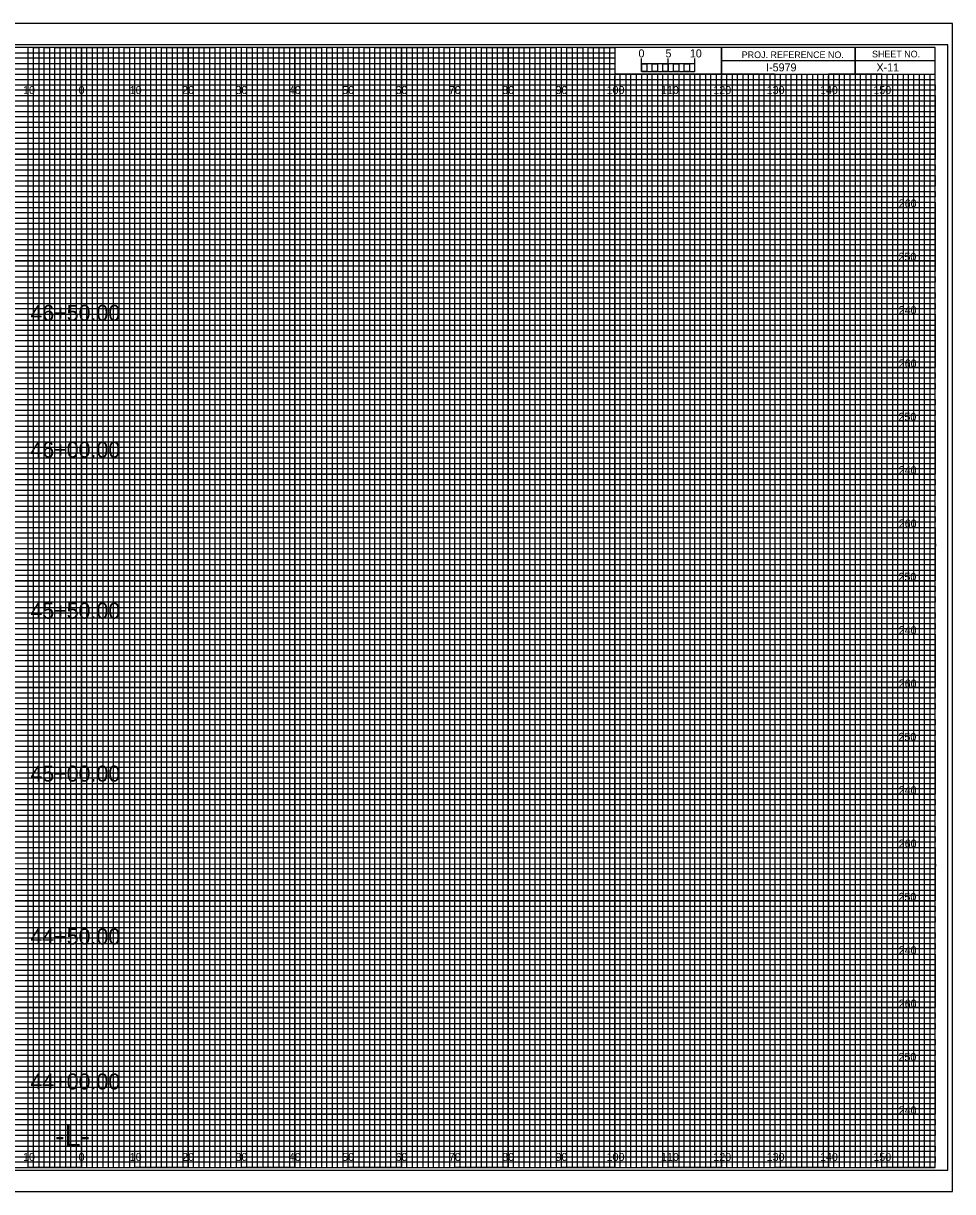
# Model space of a CAD drawing. Extents: x -13 to 359, y -5 to 2854.
# Drawn here: x 149.1 to 323.3, y 2195.5 to 2414.5 of the extents above; entities that cross this region are included whole.
import ezdxf

# ---------------------------------------------------------------- set-up
doc = ezdxf.new("R2010")
doc.units = 0
for name, color, linetype in [('Exist CMT Pavement', 7, 'Continuous'), ('Exist Cross Section Cell', 7, 'Continuous'), ('Exist XS Ground Line', 7, 'Continuous'), ('Prop CMT Conc Surface', 7, 'Continuous'), ('Prop CMT Concrete Structures', 7, 'Continuous'), ('Prop CMT DNC', 7, 'Continuous'), ('Prop CMT Pvmt Course 1', 7, 'Continuous'), ('Prop CMT Pvmt Course 1 CG', 7, 'Continuous'), ('Prop CMT Pvmt Course 1 Wedge', 7, 'Continuous'), ('Prop CMT Pvmt Course 2', 7, 'Continuous'), ('Prop CMT Pvmt Course 2 Wedge', 7, 'Continuous'), ('Prop CMT Pvmt Course 3', 7, 'Continuous'), ('Prop CMT Pvmt Course 3 Wedge', 7, 'Continuous'), ('Prop CMT Shear Line', 7, 'Continuous'), ('Prop CMT Slope Grass', 7, 'Continuous'), ('Prop CMT Subgrade Earthwork', 7, 'Continuous'), ('Scratch_Level_0', 7, 'Continuous')]:
    doc.layers.add(name, color=color, linetype=linetype)

msp = doc.modelspace()

# ---------------------------------------------------------------- linework, layer by layer
at = {"layer": 'Exist XS Ground Line'}
for p, q in [((150, 2410), (140, 2410)), ((150, 2200), (150, 2410)), ((170, 2410), (160, 2410)), ((160, 2410), (160, 2200)), ((170, 2200), (170, 2410)), ((190, 2410), (180, 2410)), ((180, 2410), (180, 2200)), ((190, 2200), (190, 2410)), ((210, 2410), (200, 2410)), ((200, 2410), (200, 2200)), ((210, 2200), (210, 2410)), ((230, 2410), (220, 2410)), ((220, 2410), (220, 2200)), ((230, 2200), (230, 2410)), ((250, 2410), (240, 2410)), ((240, 2410), (240, 2200)), ((250, 2200), (250, 2410)), ((260, 2410), (260, 2200)), ((270, 2200), (270, 2405)), ((290, 2405), (280, 2405)), ((280, 2405), (280, 2200)), ((290, 2200), (290, 2405)), ((310, 2405), (300, 2405)), ((300, 2405), (300, 2200)), ((310, 2200), (310, 2405)), ((160, 2200), (150, 2200)), ((180, 2200), (170, 2200)), ((200, 2200), (190, 2200)), ((220, 2200), (210, 2200)), ((240, 2200), (230, 2200)), ((260, 2200), (250, 2200)), ((280, 2200), (270, 2200)), ((300, 2200), (290, 2200)), ((320, 2200), (310, 2200)), ((320, 2200), (320, 2200))]:
    msp.add_line(p, q, dxfattribs=at)
for points in [[(0, 2400), (320, 2400), (320, 2390), (0, 2390)], [(0, 2380), (320, 2380), (320, 2370), (0, 2370)], [(0, 2360), (320, 2360), (320, 2350), (0, 2350)], [(0, 2340), (320, 2340), (320, 2330), (0, 2330)], [(0, 2320), (320, 2320), (320, 2310), (0, 2310)], [(0, 2300), (320, 2300), (320, 2290), (0, 2290)], [(0, 2280), (320, 2280), (320, 2270), (0, 2270)], [(0, 2260), (320, 2260), (320, 2250), (0, 2250)], [(0, 2240), (320, 2240), (320, 2230), (0, 2230)], [(0, 2220), (320, 2220), (320, 2210), (0, 2210)]]:
    msp.add_lwpolyline(points, dxfattribs=at)
at = {"layer": 'Prop CMT Conc Surface'}
for p, q in [((265, 2405.49), (265, 2407.9)), ((265, 2406.9), (265, 2407.9)), ((270, 2405.49), (270, 2407.9)), ((275, 2405.49), (275, 2407.9)), ((275, 2406.9), (275, 2407.9))]:
    msp.add_line(p, q, dxfattribs=at)
for points in [[(275, 2406.9), (265, 2406.9), (265, 2405.49), (275, 2405.49)], [(265, 2406.9), (266, 2406.9), (266, 2405.49), (265, 2405.49)], [(267, 2406.9), (268, 2406.9), (268, 2405.49), (267, 2405.49)], [(269, 2406.9), (270, 2406.9), (270, 2405.49), (269, 2405.49)], [(271, 2406.9), (272, 2406.9), (272, 2405.49), (271, 2405.49)], [(273, 2406.9), (274, 2406.9), (274, 2405.49), (273, 2405.49)]]:
    msp.add_lwpolyline(points, close=True, dxfattribs=at)
at = {"layer": 'Prop CMT Concrete Structures'}
for p, q in [((305, 2410), (305, 2405)), ((305, 2405), (305, 2410)), ((280, 2407.5), (280, 2405)), ((320, 2407.49), (280, 2407.49)), ((280, 2405), (320, 2405))]:
    msp.add_line(p, q, dxfattribs=at)
for points in [[(320, 2410), (0, 2410), (0, 2200), (320, 2200)], [(280, 2410), (260, 2410), (260, 2405.03), (280, 2405.03)], [(320, 2410), (280, 2410), (280, 2405), (320, 2405)]]:
    msp.add_lwpolyline(points, close=True, dxfattribs=at)
at = {"layer": 'Prop CMT DNC'}
for p, q in [((323.3, 2414.5), (-13.4, 2414.5)), ((-13.4, 2195.5), (323.3, 2195.5))]:
    msp.add_line(p, q, dxfattribs=at)
at = {"layer": 'Prop CMT Pvmt Course 1'}
for p, q in [((0, 2409), (260, 2409)), ((260, 2409), (260, 2407.98)), ((260, 2407.98), (0, 2407.98)), ((0, 2407), (260, 2407)), ((260, 2407), (260, 2405.89)), ((260, 2405.89), (0, 2405.89)), ((0, 2404), (320, 2404))]:
    msp.add_line(p, q, dxfattribs=at)
for points in [[(0, 2403), (270, 2403), (320, 2403), (320, 2402), (0, 2402)], [(0, 2401), (320, 2401), (320, 2399), (0, 2399)], [(0, 2398), (320, 2398), (320, 2397), (0, 2396.98)], [(0, 2396), (320, 2396), (320, 2394), (0, 2394)], [(0, 2393), (320, 2393), (320, 2392), (0, 2392)], [(0, 2391), (320, 2391), (320, 2389), (0, 2389)], [(0, 2388), (320, 2388), (320, 2387), (0, 2387)], [(0, 2386), (320, 2386), (320, 2384), (0, 2384)], [(0, 2383), (320, 2383), (320, 2382), (0, 2382)], [(0, 2381), (320, 2381), (320, 2379), (0, 2379)], [(0, 2378), (320, 2378), (320, 2377), (0, 2377)], [(0, 2376), (320, 2376), (320, 2373.95), (320, 2373), (320, 2372), (0, 2372)], [(0, 2374), (320, 2374), (320, 2373), (0, 2373)], [(0, 2371), (320, 2371), (320, 2369), (0, 2369.03)], [(0, 2369.03), (320, 2369), (320, 2368), (0, 2368)], [(0, 2367), (320, 2367), (320, 2366), (0, 2366)], [(0, 2364), (320, 2364), (320, 2363), (0, 2363)], [(0, 2362), (320, 2362), (320, 2361), (0, 2361)], [(-0.07, 2358.89), (320, 2358.89), (320, 2357.88), (-0.07, 2357.88)], [(0, 2357), (320, 2357), (320, 2356), (0, 2356)], [(0, 2354), (320, 2354), (320, 2353), (0, 2353)], [(0, 2352), (320, 2352), (320, 2351), (0, 2351)], [(0, 2349), (320, 2349), (320, 2348), (0, 2348)], [(0, 2347), (320, 2347), (320, 2346), (0, 2346)], [(0, 2344), (320, 2344), (320, 2343), (0, 2343)], [(0, 2342), (320, 2342), (320, 2341), (0, 2341)], [(0, 2339), (320, 2339), (319.99, 2337.98), (0, 2338)], [(0, 2337), (320, 2337), (320, 2336), (0, 2336)], [(0, 2334), (320, 2334), (320, 2333), (0, 2333)], [(0, 2332), (320, 2332), (320, 2331), (0, 2331)], [(0, 2329), (320, 2329), (320, 2328), (0, 2328)], [(0, 2327), (320, 2327), (320, 2326), (0, 2326)], [(0, 2324), (320, 2324), (320, 2323), (0, 2323)], [(0, 2322), (320, 2322), (320, 2321), (0, 2321)], [(0, 2319), (320, 2319), (320, 2318), (0, 2318)], [(0, 2316.99), (320.07, 2316.91), (320, 2316), (0, 2316)], [(0, 2314), (320, 2314), (320, 2313), (0, 2313)], [(0, 2312), (320, 2312), (320, 2311), (0, 2311)], [(0, 2309), (320, 2309), (320, 2308), (0, 2308)], [(0, 2307), (320, 2307), (320, 2306), (0, 2306)], [(0, 2304), (320, 2304), (320, 2303), (0, 2303)], [(0, 2302), (320, 2302), (320, 2301), (0, 2301)], [(0, 2299), (320, 2299), (320, 2298), (0, 2298)], [(0, 2297), (320, 2297), (320, 2296), (0, 2296)], [(0, 2294), (320, 2294), (320, 2293), (0, 2293)], [(0, 2292), (320, 2292), (320, 2291), (0, 2291)], [(0, 2289), (320, 2289), (320, 2288), (0, 2288)], [(0, 2287), (320, 2287), (320, 2286), (0, 2286)], [(0, 2284), (320, 2284), (320, 2283), (0, 2283)], [(0, 2282), (320, 2282), (320, 2281), (0, 2281)], [(0, 2279), (320, 2279), (319.99, 2277.98), (0, 2278)], [(0, 2277), (320, 2277), (320, 2276), (0, 2276)], [(0, 2274), (320, 2274), (320, 2273), (0, 2273)], [(0, 2272), (320, 2272), (320, 2271), (0, 2271)], [(0, 2269), (320, 2269), (320, 2268), (0, 2268)], [(0, 2267), (320, 2267), (320, 2266), (0, 2266)], [(0, 2264), (320, 2264), (320, 2263), (0, 2263)], [(0, 2262), (320, 2262), (320, 2261), (0, 2261)], [(0, 2259), (320, 2259), (320, 2258), (0, 2258)], [(0, 2256.99), (320.07, 2256.91), (320, 2256), (0, 2256)], [(0, 2254), (320, 2254), (320, 2253), (0, 2253)], [(0, 2252), (320, 2252), (320, 2251), (0, 2251)], [(0, 2249), (320, 2249), (320, 2248), (0, 2248)], [(0, 2247), (320, 2247), (320, 2246), (0, 2246)], [(0, 2244), (320, 2244), (320, 2243), (0, 2243)], [(0, 2242), (320, 2242), (320, 2241), (0, 2241)], [(0, 2239), (320, 2239), (320, 2238), (0, 2238)], [(0, 2237), (320, 2237), (320, 2236), (0, 2236)], [(0, 2234), (320, 2234), (320, 2233), (0, 2233)], [(0, 2232), (320, 2232), (320, 2231), (0, 2231)], [(0, 2229), (320, 2229), (320, 2228), (0, 2228)], [(0, 2227), (320, 2227), (320, 2226), (0, 2226)], [(0, 2224), (320, 2224), (320, 2223), (0, 2223)], [(0, 2222), (320, 2222), (320, 2221), (0, 2221)], [(0, 2219), (320, 2219), (320, 2218), (0, 2218)], [(0, 2217), (320, 2217), (320, 2216), (0, 2216)], [(0, 2214), (320, 2214), (320, 2213), (0, 2213)], [(0, 2212), (320, 2212), (320, 2211), (0, 2211)], [(0, 2209), (320, 2209), (320, 2208), (0, 2208)], [(0, 2207), (320, 2207), (320, 2206), (0, 2206)], [(0, 2204), (320, 2204), (320, 2203), (0, 2203)], [(0, 2202), (320, 2202), (320, 2201), (0, 2201)]]:
    msp.add_lwpolyline(points, dxfattribs=at)
at = {"layer": 'Prop CMT Pvmt Course 1 CG'}
for p, q in [((267, 2405), (266.01, 2405)), ((266.01, 2405), (266.01, 2200)), ((267, 2200), (267, 2405)), ((269, 2405), (268, 2405)), ((268, 2405), (268, 2200)), ((269, 2200), (269, 2405)), ((266.01, 2200), (265, 2200)), ((268, 2200), (267, 2200))]:
    msp.add_line(p, q, dxfattribs=at)
for points in [[(150, 2200), (151, 2200), (151, 2410), (152, 2410), (152, 2200)], [(152, 2200), (153, 2200), (153, 2410), (154, 2410), (154, 2200)], [(155, 2200), (156, 2200), (156, 2410), (157, 2410), (157, 2200)], [(157, 2200), (158, 2200), (158, 2410), (159, 2410), (159, 2200)], [(160, 2200), (161, 2200), (161, 2410), (162, 2410), (162, 2200)], [(162, 2200), (163, 2200), (163, 2410), (164, 2410), (164, 2200)], [(165, 2200), (166, 2200), (166, 2410), (167, 2410), (167, 2200)], [(167, 2200), (168, 2200), (168, 2410), (169, 2410), (169, 2200)], [(170, 2200), (171, 2200), (171, 2410), (172, 2410), (172, 2200)], [(172, 2200), (173, 2200), (173, 2410), (174, 2410), (174, 2200)], [(175, 2200), (176, 2200), (176, 2410), (177, 2410), (177, 2200)], [(177, 2200), (178, 2200), (178, 2410), (179, 2410), (179, 2200)], [(180, 2200), (181, 2200), (181, 2410), (182, 2410), (182, 2200)], [(182, 2200), (183, 2200), (183, 2410), (184, 2410), (184, 2200)], [(185, 2200), (186, 2200), (186, 2410), (187, 2410), (187, 2200)], [(187, 2200), (188, 2200), (188, 2410), (189, 2410), (189, 2200)], [(190, 2200), (191, 2200), (191, 2410), (192, 2410), (192, 2200)], [(192, 2200), (193, 2200), (193, 2410), (194, 2410), (194, 2200)], [(195, 2200), (196, 2200), (196, 2410), (197, 2410), (197, 2200)], [(197, 2200), (198, 2200), (198, 2410), (199, 2410), (199, 2200)], [(200, 2200), (201, 2200), (201, 2410), (202, 2410), (202, 2200)], [(202, 2200), (203, 2200), (203, 2410), (204, 2410), (204, 2200)], [(205, 2200), (206, 2200), (206, 2410), (207, 2410), (207, 2200)], [(207, 2200), (208, 2200), (208, 2410), (209, 2410), (209, 2200)], [(210, 2200), (211, 2200), (211, 2410), (212, 2410), (212, 2200)], [(212, 2200), (213, 2200), (213, 2410), (214, 2410), (214, 2200)], [(215, 2200), (216, 2200), (216, 2410), (217, 2410), (217, 2200)], [(217, 2200), (218, 2200), (218, 2410), (219, 2410), (219, 2200)], [(220, 2200), (221, 2200), (221, 2410), (222, 2410), (222, 2200)], [(222, 2200), (223, 2200), (223, 2410), (224, 2410), (224, 2200)], [(225, 2200), (226, 2200), (226, 2410), (227, 2410), (227, 2200)], [(227, 2200), (228, 2200), (228, 2410), (229, 2410), (229, 2200)], [(230, 2200), (231, 2200), (231, 2410), (232, 2410), (232, 2200)], [(232, 2200), (233, 2200), (233, 2410), (234, 2410), (234, 2200)], [(235, 2200), (236, 2200), (236, 2410), (237, 2410), (237, 2200)], [(237, 2200), (238, 2200), (238, 2410), (239, 2410), (239, 2200)], [(240, 2200), (241, 2200), (241, 2410), (242, 2410), (242, 2200)], [(242, 2200), (243, 2200), (243, 2410), (244, 2410), (244, 2200)], [(245, 2200), (246, 2200), (246, 2410), (247, 2410), (247, 2200)], [(247, 2200), (248, 2200), (248, 2410), (249, 2410), (249, 2200)], [(250, 2200), (251, 2200), (251, 2410), (252, 2410), (252, 2200)], [(252, 2200), (253, 2200), (253, 2410), (254, 2410), (254, 2200)], [(255, 2200), (256, 2200), (256, 2410), (257, 2410), (257, 2200)], [(257, 2200), (258, 2200), (258, 2410), (259, 2410), (259, 2200)], [(260, 2200), (261, 2200), (261, 2405), (262.02, 2405), (262.02, 2200)], [(262, 2200), (263, 2200), (263, 2405), (263.99, 2405), (263.99, 2200)], [(270, 2200), (270.98, 2200), (270.98, 2405), (272, 2405), (272, 2200)], [(272, 2200), (273, 2200), (273, 2405), (274.05, 2405), (274.05, 2200)], [(275, 2200), (276, 2200), (276, 2405), (277, 2405), (277, 2200)], [(277, 2200), (278, 2200), (278, 2405), (279, 2405), (279, 2200)], [(280, 2200), (281, 2200), (281, 2405), (282, 2405), (282, 2200)], [(282, 2200), (283, 2200), (283, 2405), (284, 2405), (284, 2200)], [(285, 2200), (286, 2200), (286, 2405), (287, 2405), (287, 2200)], [(287, 2200), (288, 2200), (288, 2405), (289, 2405), (289, 2200)], [(290, 2200), (291, 2200), (291, 2405), (292, 2405), (292, 2200)], [(292, 2200), (293, 2200), (293, 2405), (294, 2405), (294, 2200)], [(295, 2200), (296, 2200), (296, 2405), (297, 2405), (297, 2200)], [(297, 2200), (298, 2200), (298, 2405), (299, 2405), (299, 2200)], [(300, 2200), (301, 2200), (301, 2405), (302, 2405), (302, 2200)], [(302, 2200), (303, 2200), (303, 2405), (304, 2405), (304, 2200)], [(305, 2200), (306, 2200), (306, 2405), (307, 2405), (307, 2200)], [(307, 2200), (308, 2200), (308, 2405), (309, 2405), (309, 2200)], [(310, 2200), (311, 2200), (311, 2405), (312, 2405), (312, 2200)], [(312, 2200), (313, 2200), (313, 2405), (314, 2405), (314, 2200)], [(315, 2200), (316, 2200), (316, 2405), (317, 2405), (317, 2200)], [(317, 2200), (318, 2200), (318, 2405), (319, 2405), (319, 2200)]]:
    msp.add_lwpolyline(points, dxfattribs=at)
at = {"layer": 'Prop CMT Shear Line'}
for p, q in [((150, 2200), (150, 2410)), ((160, 2200), (160, 2410)), ((170, 2200), (170, 2410)), ((180, 2200), (180, 2410)), ((190, 2200), (190, 2410)), ((200, 2200), (200, 2410)), ((210, 2200), (210, 2410)), ((220, 2200), (220, 2410)), ((230, 2200), (230, 2410)), ((240, 2200), (240, 2410)), ((250, 2200), (250, 2410)), ((260, 2200), (260, 2404.69)), ((270, 2200), (270, 2404.69)), ((280, 2200), (280, 2404.69)), ((290, 2200), (290, 2404.69)), ((300, 2200), (300, 2404.69)), ((310, 2200), (310, 2404.69)), ((0, 2400), (320, 2400)), ((0, 2390), (320, 2390)), ((0, 2380), (320, 2380)), ((0, 2370), (320, 2370)), ((0, 2360), (320, 2360)), ((0, 2350), (320, 2350)), ((0, 2340), (320, 2340)), ((0, 2330), (320, 2330)), ((0, 2320), (320, 2320)), ((0, 2310), (320, 2310)), ((0, 2300), (320, 2300)), ((0, 2290), (320, 2290)), ((0, 2280), (320, 2280)), ((0, 2270), (320, 2270)), ((0, 2260), (320, 2260)), ((0, 2250), (320, 2250)), ((0, 2240), (320, 2240)), ((0, 2230), (320, 2230)), ((0, 2220), (320, 2220)), ((0, 2210), (320, 2210))]:
    msp.add_line(p, q, dxfattribs=at)
at = {"layer": 'Prop CMT Slope Grass'}
msp.add_lwpolyline([(-10.8, 2199.5), (322.4, 2199.5), (322.4, 2410.5), (-10.8, 2410.5)], close=True, dxfattribs=at)
at = {"layer": 'Prop CMT Subgrade Earthwork'}
msp.add_lwpolyline([(-13.4, 2195.5), (323.3, 2195.5), (323.3, 2414.5), (-13.4, 2414.5)], close=True, dxfattribs=at)
at = {"layer": 'Scratch_Level_0'}
for points in [[(145, 2200), (155, 2200), (155, 2410), (165, 2410), (165, 2200), (175, 2200), (175, 2410), (185, 2410), (185, 2200), (195, 2200), (195, 2410), (205, 2410), (205, 2200), (215, 2200), (215, 2410), (225, 2410), (225, 2200), (235, 2200), (235, 2410), (245, 2410), (245, 2200), (255, 2200), (255, 2410), (259.93, 2410), (260, 2410), (260, 2405), (264.99, 2405), (264.99, 2200), (275, 2200), (275, 2405), (285, 2405), (285, 2200), (295, 2200), (295, 2405), (305, 2405), (305, 2200), (315, 2200), (315, 2405)], [(0, 2405), (275, 2405)], [(0, 2385), (320, 2385), (320, 2395), (0, 2395)], [(0, 2365), (320, 2365), (320, 2375), (0, 2375)], [(0, 2345), (320, 2345), (320, 2355), (0, 2355)], [(0, 2325), (320, 2325), (320, 2335), (0, 2335)], [(0, 2305), (320, 2305), (320, 2315), (0, 2315)], [(0, 2285), (320, 2285), (320, 2295), (0, 2295)], [(0, 2265), (320, 2265), (320, 2275), (0, 2275)], [(0, 2245), (320, 2245), (320, 2255), (0, 2255)], [(0, 2225), (320, 2225), (320, 2235), (0, 2235)], [(0, 2205), (320, 2205), (320, 2215), (0, 2215)]]:
    msp.add_lwpolyline(points, dxfattribs=at)

# ---------------------------------------------------------------- texts
at = {"layer": 'Exist CMT Pavement'}
for s, p in [('5', (269.47, 2408.12)), ('10', (274.04, 2408.12))]:
    msp.add_text(s, height=1.5, dxfattribs=at).set_placement(p)
at = {"layer": 'Exist Cross Section Cell'}
for s, p in [('10', (149.04, 2401.25)), ('0', (159.45, 2401.25)), ('0', (159.45, 2401.25)), ('10', (169.04, 2401.25)), ('20', (178.86, 2401.25)), ('30', (188.86, 2401.25)), ('40', (198.86, 2401.25)), ('50', (208.86, 2401.25)), ('60', (218.86, 2401.25)), ('70', (228.86, 2401.25)), ('80', (238.86, 2401.25)), ('90', (248.86, 2401.25)), ('100', (258.44, 2401.25)), ('110', (268.62, 2401.25)), ('120', (278.44, 2401.25)), ('130', (288.44, 2401.25)), ('140', (298.44, 2401.25)), ('150', (308.44, 2401.25)), ('10', (149.04, 2201.25)), ('0', (159.45, 2201.25)), ('0', (159.45, 2201.25)), ('10', (169.04, 2201.25)), ('20', (178.86, 2201.25)), ('30', (188.86, 2201.25)), ('40', (198.86, 2201.25)), ('50', (208.86, 2201.25)), ('60', (218.86, 2201.25)), ('70', (228.86, 2201.25)), ('80', (238.86, 2201.25)), ('90', (248.86, 2201.25)), ('100', (258.44, 2201.25)), ('110', (268.62, 2201.25)), ('120', (278.44, 2201.25)), ('130', (288.44, 2201.25)), ('140', (298.44, 2201.25)), ('150', (308.44, 2201.25))]:
    msp.add_text(s, height=1.5, dxfattribs=at).set_placement(p)
at = {"layer": 'Prop CMT Conc Surface'}
msp.add_text('0', height=1.5, dxfattribs=at).set_placement((264.41, 2408.12))
at = {"layer": 'Prop CMT Concrete Structures'}
for s, p in [('PROJ. REFERENCE NO.', (283.77, 2407.99)), ('SHEET NO.', (308.19, 2408.12))]:
    msp.add_text(s, height=1.25, dxfattribs=at).set_placement(p)
at = {"layer": 'Prop CMT Pvmt Course 1 Wedge'}
msp.add_text('X-11', height=1.5, dxfattribs=at).set_placement((309.02, 2405.5))
at = {"layer": 'Prop CMT Pvmt Course 2'}
for s, p in [('260', (313.19, 2380)), ('250', (313.15, 2370)), ('240', (313.19, 2360)), ('260', (313.19, 2350)), ('250', (313.15, 2340)), ('240', (313.19, 2330)), ('260', (313.19, 2320)), ('250', (313.15, 2310)), ('240', (313.19, 2300)), ('260', (313.19, 2290)), ('250', (313.15, 2280)), ('240', (313.19, 2270)), ('260', (313.19, 2260)), ('250', (313.15, 2250)), ('240', (313.19, 2240)), ('260', (313.19, 2230)), ('250', (313.15, 2220)), ('240', (313.19, 2210))]:
    msp.add_text(s, height=1.5, dxfattribs=at).set_placement(p)
at = {"layer": 'Prop CMT Pvmt Course 2 Wedge'}
msp.add_text('I-5979', height=1.5, dxfattribs=at).set_placement((288.34, 2405.5))
at = {"layer": 'Prop CMT Pvmt Course 3'}
for s, p in [('46+50.00', (150.41, 2358.73)), ('46+00.00', (150.41, 2333.09)), ('45+50.00', (150.41, 2302.9)), ('45+00.00', (150.41, 2272.36)), ('44+50.00', (150.41, 2241.84)), ('44+00.00', (150.41, 2214.65))]:
    msp.add_text(s, height=3, dxfattribs=at).set_placement(p)
at = {"layer": 'Prop CMT Pvmt Course 3 Wedge'}
msp.add_text('-L-', height=4, dxfattribs=at).set_placement((155.06, 2204))

doc.saveas('drawing.dxf')
